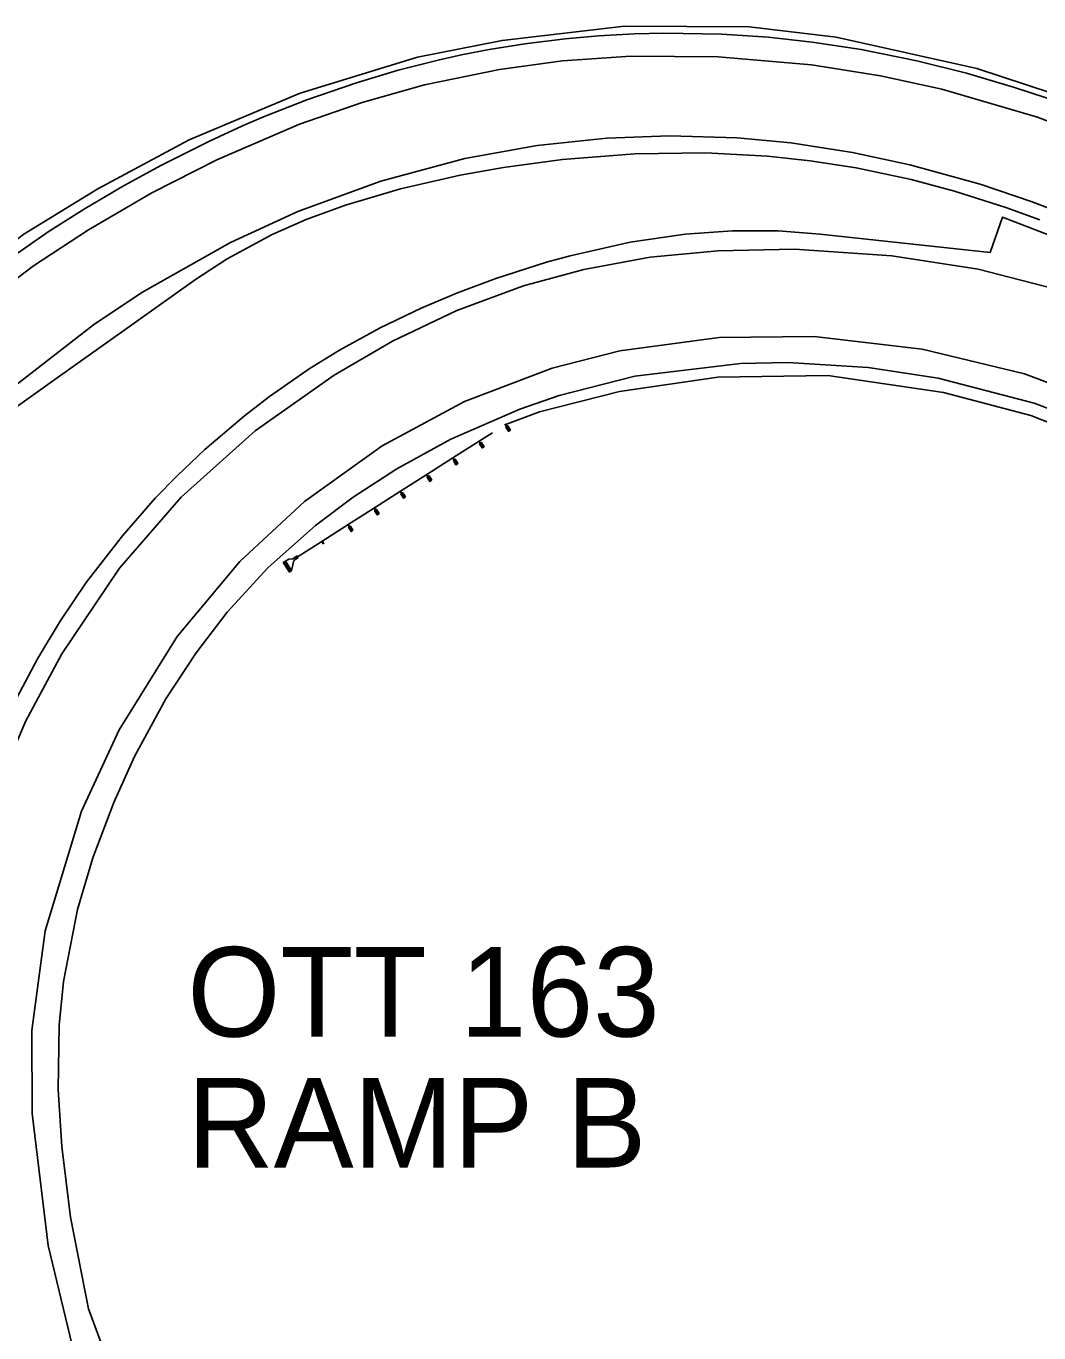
# Model space of a CAD drawing. Extents: x 1855721 to 1876784, y 662259 to 674089.
# Drawn here: x 1856144.7 to 1856348.3, y 673826.6 to 674089.3 of the extents above; entities that cross this region are included whole.
import ezdxf

# ---------------------------------------------------------------- set-up
doc = ezdxf.new("R2010")
doc.units = 0
for name, color, linetype in [('_CIVIL_CONSTRUCTION', 7, 'Continuous'), ('GE_X_Alignment_100_Curve_Data', 7, 'Continuous'), ('RD_P_Anchor_Assembly', 7, 'Continuous'), ('RD_P_GR_Rt', 7, 'Continuous'), ('SC_Scratch1', 7, 'Continuous')]:
    doc.layers.add(name, color=color, linetype=linetype)

msp = doc.modelspace()

# ---------------------------------------------------------------- linework, layer by layer
at = {"layer": '_CIVIL_CONSTRUCTION'}
for points in [[(1856365.83, 674064.19), (1856348.04, 674071.01), (1856328.81, 674076.64), (1856316.49, 674079.35), (1856302.61, 674081.57), (1856283.82, 674083.19), (1856266.25, 674083.26), (1856252.53, 674082.32), (1856239.87, 674080.62), (1856224.82, 674077.52), (1856212.28, 674073.99), (1856199.69, 674069.59), (1856183.06, 674062.46), (1856170, 674055.82), (1856157.25, 674048.4), (1856146.21, 674041.12), (1856132.47, 674030.72)], [(1856153.97, 673824.06), (1856149.12, 673844.11), (1856145.94, 673870.67), (1856145.86, 673887.35), (1856148.51, 673907.38), (1856155.85, 673931.44), (1856163.44, 673947.84), (1856175.09, 673966.57), (1856187.67, 673981.7), (1856200.69, 673993.76), (1856216.3, 674004.93), (1856232.86, 674013.82), (1856250.47, 674020.54), (1856264.09, 674024.02), (1856284, 674026.71), (1856303.15, 674026.89), (1856324.84, 674024.4), (1856345.43, 674019.44), (1856368.74, 674010.66)]]:
    msp.add_lwpolyline(points, dxfattribs=at)
at = {"layer": 'GE_X_Alignment_100_Curve_Data'}
for points in [[(1856023.41, 673851.89), (1856068.46, 673924.1), (1856079.99, 673941.29), (1856102.7, 673972.55), (1856111.82, 673984.94), (1856127.2, 674002.68), (1856142.37, 674016.93), (1856158.23, 674029.27), (1856167.96, 674035.77), (1856185.8, 674045.85), (1856199.32, 674052.06), (1856215.99, 674058.15), (1856232.89, 674062.69), (1856247.41, 674065.32), (1856261.44, 674066.8), (1856274.02, 674067.27), (1856287.62, 674066.87), (1856298.45, 674065.86), (1856310.85, 674063.95), (1856322.36, 674061.47), (1856336.49, 674057.55), (1856346.97, 674054.03), (1856357.92, 674049.8)], [(1856353.26, 674036.03), (1856336.07, 674040.44), (1856318.76, 674043.17), (1856299.16, 674044.45), (1856283.75, 674044.17), (1856270.16, 674042.84), (1856256.79, 674040.42), (1856244.68, 674037.12), (1856231.3, 674032.13), (1856218.37, 674025.96), (1856206.65, 674019.17), (1856190.78, 674007.98), (1856175.89, 673994.63), (1856163.5, 673980.36), (1856151.87, 673963.08), (1856144.68, 673949.64), (1856137.78, 673933.6), (1856132.13, 673915.51), (1856129.25, 673901.08), (1856127.96, 673888.15), (1856127.91, 673872.04), (1856129.26, 673855.64), (1856131.43, 673840.51), (1856134.42, 673826.04)]]:
    msp.add_lwpolyline(points, dxfattribs=at)
at = {"layer": 'RD_P_Anchor_Assembly'}
for p, q in [((1856240.93, 674009.13), (1856241.2, 674009.31)), ((1856240.93, 674009.13), (1856240.94, 674009.12)), ((1856240.94, 674009.12), (1856241.07, 674009.2)), ((1856241.07, 674009.2), (1856241.31, 674008.82)), ((1856241.08, 674009.21), (1856241.21, 674009.3)), ((1856241.08, 674009.21), (1856241.33, 674008.83)), ((1856241.13, 674008.71), (1856241.16, 674008.73)), ((1856241.66, 674007.86), (1856241.13, 674008.7)), ((1856241.15, 674008.84), (1856241.2, 674008.88)), ((1856241.15, 674008.84), (1856241.22, 674008.74)), ((1856241.16, 674008.81), (1856241.23, 674008.86)), ((1856241.16, 674008.74), (1856241.29, 674008.82)), ((1856241.19, 674008.75), (1856241.16, 674008.8)), ((1856241.17, 674008.73), (1856241.16, 674008.74)), ((1856241.18, 674008.71), (1856241.16, 674008.73)), ((1856241.18, 674008.71), (1856241.48, 674008.9)), ((1856241.18, 674008.73), (1856241.31, 674008.82)), ((1856241.18, 674008.73), (1856241.19, 674008.72)), ((1856241.19, 674008.72), (1856241.47, 674008.9)), ((1856241.2, 674009.31), (1856241.21, 674009.3)), ((1856241.2, 674008.88), (1856241.27, 674008.77)), ((1856241.75, 674007.9), (1856241.22, 674008.74)), ((1856241.27, 674008.81), (1856241.24, 674008.85)), ((1856241.81, 674007.94), (1856241.27, 674008.77)), ((1856241.3, 674008.81), (1856241.29, 674008.82)), ((1856241.33, 674008.83), (1856241.46, 674008.91)), ((1856241.46, 674008.91), (1856241.47, 674008.9)), ((1856241.47, 674008.92), (1856241.5, 674008.95)), ((1856241.48, 674008.9), (1856241.47, 674008.92)), ((1856242.05, 674008.1), (1856241.52, 674008.94)), ((1856241.68, 674007.85), (1856242.05, 674008.09)), ((1856230.52, 674002.51), (1856235.79, 674005.87)), ((1856235.65, 674005.78), (1856235.93, 674005.95)), ((1856235.65, 674005.78), (1856235.66, 674005.76)), ((1856235.66, 674005.76), (1856235.8, 674005.85)), ((1856235.79, 674005.87), (1856238.43, 674007.54)), ((1856235.8, 674005.85), (1856236.04, 674005.46)), ((1856235.81, 674005.85), (1856235.94, 674005.94)), ((1856235.81, 674005.85), (1856236.05, 674005.47)), ((1856235.86, 674005.35), (1856235.89, 674005.37)), ((1856236.39, 674004.5), (1856235.86, 674005.34)), ((1856235.88, 674005.49), (1856235.93, 674005.52)), ((1856235.88, 674005.49), (1856235.95, 674005.38)), ((1856235.89, 674005.46), (1856235.95, 674005.5)), ((1856235.89, 674005.38), (1856236.02, 674005.47)), ((1856235.91, 674005.4), (1856235.89, 674005.44)), ((1856235.9, 674005.37), (1856235.89, 674005.38)), ((1856235.91, 674005.35), (1856235.89, 674005.37)), ((1856235.91, 674005.35), (1856236.21, 674005.55)), ((1856235.91, 674005.38), (1856236.04, 674005.46)), ((1856235.91, 674005.38), (1856235.92, 674005.36)), ((1856235.92, 674005.36), (1856236.2, 674005.54)), ((1856235.93, 674005.95), (1856235.94, 674005.94)), ((1856235.93, 674005.52), (1856236, 674005.41)), ((1856236.48, 674004.54), (1856235.95, 674005.38)), ((1856236, 674005.45), (1856235.97, 674005.49)), ((1856236.53, 674004.58), (1856236, 674005.41)), ((1856236.03, 674005.45), (1856236.02, 674005.47)), ((1856236.05, 674005.47), (1856236.19, 674005.55)), ((1856236.19, 674005.55), (1856236.2, 674005.54)), ((1856236.2, 674005.57), (1856236.23, 674005.59)), ((1856236.21, 674005.55), (1856236.2, 674005.57)), ((1856236.78, 674004.75), (1856236.24, 674005.59)), ((1856225.25, 673999.15), (1856230.52, 674002.51)), ((1856230.38, 674002.42), (1856230.66, 674002.6)), ((1856230.38, 674002.42), (1856230.39, 674002.41)), ((1856230.39, 674002.41), (1856230.53, 674002.49)), ((1856230.53, 674002.49), (1856230.77, 674002.1)), ((1856230.54, 674002.5), (1856230.67, 674002.58)), ((1856230.54, 674002.5), (1856230.78, 674002.11)), ((1856230.66, 674002.6), (1856230.67, 674002.58)), ((1856236.41, 674004.5), (1856236.78, 674004.73)), ((1856230.59, 674002), (1856230.62, 674002.02)), ((1856231.12, 674001.14), (1856230.59, 674001.98)), ((1856230.61, 674002.13), (1856230.66, 674002.16)), ((1856230.61, 674002.13), (1856230.68, 674002.02)), ((1856230.62, 674002.1), (1856230.68, 674002.14)), ((1856230.62, 674002.02), (1856230.75, 674002.11)), ((1856230.64, 674002.04), (1856230.62, 674002.08)), ((1856230.63, 674002.01), (1856230.62, 674002.02)), ((1856230.63, 674002), (1856230.62, 674002.02)), ((1856230.63, 674002), (1856230.94, 674002.19)), ((1856230.64, 674002.02), (1856230.77, 674002.1)), ((1856230.64, 674002.02), (1856230.65, 674002.01)), ((1856230.65, 674002.01), (1856230.92, 674002.18)), ((1856230.66, 674002.16), (1856230.73, 674002.06)), ((1856231.21, 674001.19), (1856230.68, 674002.02)), ((1856230.72, 674002.09), (1856230.7, 674002.14)), ((1856231.26, 674001.22), (1856230.73, 674002.06)), ((1856230.76, 674002.1), (1856230.75, 674002.11)), ((1856230.78, 674002.11), (1856230.92, 674002.2)), ((1856230.92, 674002.2), (1856230.92, 674002.18)), ((1856230.93, 674002.21), (1856230.96, 674002.23)), ((1856230.94, 674002.19), (1856230.93, 674002.21)), ((1856231.51, 674001.39), (1856230.97, 674002.23)), ((1856231.13, 674001.14), (1856231.5, 674001.38)), ((1856219.98, 673995.79), (1856225.25, 673999.15)), ((1856225.11, 673999.06), (1856225.39, 673999.24)), ((1856225.11, 673999.06), (1856225.12, 673999.05)), ((1856225.12, 673999.05), (1856225.25, 673999.13)), ((1856225.25, 673999.13), (1856225.5, 673998.75)), ((1856225.27, 673999.14), (1856225.4, 673999.22)), ((1856225.27, 673999.14), (1856225.51, 673998.76)), ((1856225.85, 673997.79), (1856225.31, 673998.62)), ((1856225.32, 673998.64), (1856225.35, 673998.66)), ((1856225.34, 673998.77), (1856225.39, 673998.81)), ((1856225.34, 673998.74), (1856225.41, 673998.78)), ((1856225.34, 673998.77), (1856225.4, 673998.67)), ((1856225.37, 673998.68), (1856225.34, 673998.73)), ((1856225.35, 673998.67), (1856225.48, 673998.75)), ((1856225.35, 673998.66), (1856225.35, 673998.67)), ((1856225.36, 673998.64), (1856225.35, 673998.66)), ((1856225.36, 673998.64), (1856225.67, 673998.83)), ((1856225.37, 673998.66), (1856225.5, 673998.75)), ((1856225.37, 673998.66), (1856225.38, 673998.65)), ((1856225.38, 673998.65), (1856225.65, 673998.82)), ((1856225.39, 673999.24), (1856225.4, 673999.22)), ((1856225.39, 673998.81), (1856225.46, 673998.7)), ((1856225.94, 673997.83), (1856225.4, 673998.67)), ((1856225.45, 673998.74), (1856225.43, 673998.78)), ((1856225.99, 673997.86), (1856225.46, 673998.7)), ((1856225.49, 673998.74), (1856225.48, 673998.75)), ((1856225.51, 673998.76), (1856225.64, 673998.84)), ((1856225.64, 673998.84), (1856225.65, 673998.82)), ((1856225.65, 673998.85), (1856225.69, 673998.87)), ((1856225.67, 673998.83), (1856225.65, 673998.85)), ((1856226.24, 673998.03), (1856225.7, 673998.87)), ((1856225.86, 673997.78), (1856226.23, 673998.02)), ((1856214.71, 673992.44), (1856219.98, 673995.79)), ((1856219.84, 673995.71), (1856220.12, 673995.88)), ((1856219.84, 673995.71), (1856219.85, 673995.69)), ((1856219.85, 673995.69), (1856219.98, 673995.78)), ((1856219.98, 673995.78), (1856220.23, 673995.39)), ((1856219.99, 673995.78), (1856220.13, 673995.87)), ((1856219.99, 673995.78), (1856220.24, 673995.4)), ((1856220.04, 673995.28), (1856220.08, 673995.3)), ((1856220.58, 673994.43), (1856220.04, 673995.27)), ((1856220.06, 673995.42), (1856220.12, 673995.45)), ((1856220.06, 673995.42), (1856220.13, 673995.31)), ((1856220.07, 673995.38), (1856220.14, 673995.43)), ((1856220.07, 673995.31), (1856220.21, 673995.39)), ((1856220.1, 673995.33), (1856220.07, 673995.37)), ((1856220.08, 673995.3), (1856220.07, 673995.31)), ((1856220.09, 673995.28), (1856220.08, 673995.3)), ((1856220.09, 673995.28), (1856220.39, 673995.48)), ((1856220.09, 673995.31), (1856220.23, 673995.39)), ((1856220.09, 673995.31), (1856220.1, 673995.29)), ((1856220.1, 673995.29), (1856220.38, 673995.47)), ((1856220.12, 673995.88), (1856220.13, 673995.87)), ((1856220.12, 673995.45), (1856220.19, 673995.34)), ((1856220.66, 673994.47), (1856220.13, 673995.31)), ((1856220.18, 673995.38), (1856220.15, 673995.42)), ((1856220.72, 673994.51), (1856220.19, 673995.34)), ((1856220.21, 673995.38), (1856220.21, 673995.39)), ((1856220.24, 673995.4), (1856220.37, 673995.48)), ((1856220.37, 673995.48), (1856220.38, 673995.47)), ((1856220.38, 673995.5), (1856220.42, 673995.52)), ((1856220.39, 673995.48), (1856220.38, 673995.5)), ((1856220.96, 673994.67), (1856220.43, 673995.51)), ((1856220.59, 673994.42), (1856220.96, 673994.66)), ((1856209.43, 673989.08), (1856214.71, 673992.44)), ((1856214.57, 673992.35), (1856214.84, 673992.53)), ((1856214.57, 673992.35), (1856214.58, 673992.33)), ((1856214.58, 673992.33), (1856214.71, 673992.42)), ((1856214.71, 673992.42), (1856214.96, 673992.03)), ((1856214.72, 673992.43), (1856214.85, 673992.51)), ((1856214.72, 673992.43), (1856214.97, 673992.04)), ((1856214.77, 673991.92), (1856214.81, 673991.94)), ((1856215.3, 673991.07), (1856214.77, 673991.91)), ((1856214.79, 673992.06), (1856214.85, 673992.09)), ((1856214.79, 673992.06), (1856214.86, 673991.95)), ((1856214.8, 673992.03), (1856214.87, 673992.07)), ((1856214.8, 673991.95), (1856214.93, 673992.04)), ((1856214.83, 673991.97), (1856214.8, 673992.01)), ((1856214.81, 673991.94), (1856214.8, 673991.95)), ((1856214.82, 673991.92), (1856214.81, 673991.94)), ((1856214.82, 673991.92), (1856215.12, 673992.12)), ((1856214.82, 673991.95), (1856214.96, 673992.03)), ((1856214.82, 673991.95), (1856214.83, 673991.93)), ((1856214.83, 673991.93), (1856215.11, 673992.11)), ((1856214.84, 673992.53), (1856214.85, 673992.51)), ((1856214.85, 673992.09), (1856214.91, 673991.99)), ((1856215.39, 673991.12), (1856214.86, 673991.95)), ((1856214.91, 673992.02), (1856214.88, 673992.06)), ((1856215.45, 673991.15), (1856214.91, 673991.99)), ((1856214.94, 673992.02), (1856214.93, 673992.04)), ((1856214.97, 673992.04), (1856215.1, 673992.13)), ((1856215.1, 673992.13), (1856215.11, 673992.11)), ((1856215.11, 673992.14), (1856215.14, 673992.16)), ((1856215.12, 673992.12), (1856215.11, 673992.14)), ((1856215.69, 673991.32), (1856215.16, 673992.16)), ((1856215.32, 673991.07), (1856215.69, 673991.3)), ((1856204.16, 673985.72), (1856209.43, 673989.08)), ((1856209.3, 673988.99), (1856209.57, 673989.17)), ((1856209.3, 673988.99), (1856209.31, 673988.98)), ((1856209.31, 673988.98), (1856209.44, 673989.06)), ((1856209.44, 673989.06), (1856209.68, 673988.68)), ((1856209.45, 673989.07), (1856209.58, 673989.15)), ((1856209.45, 673989.07), (1856209.7, 673988.68)), ((1856209.5, 673988.57), (1856209.53, 673988.59)), ((1856210.03, 673987.71), (1856209.5, 673988.55)), ((1856209.52, 673988.7), (1856209.57, 673988.73)), ((1856209.52, 673988.7), (1856209.59, 673988.59)), ((1856209.53, 673988.67), (1856209.6, 673988.71)), ((1856209.53, 673988.6), (1856209.66, 673988.68)), ((1856209.55, 673988.61), (1856209.53, 673988.65)), ((1856209.54, 673988.58), (1856209.53, 673988.6)), ((1856209.55, 673988.57), (1856209.53, 673988.59)), ((1856209.55, 673988.57), (1856209.85, 673988.76)), ((1856209.55, 673988.59), (1856209.68, 673988.68)), ((1856209.55, 673988.59), (1856209.56, 673988.58)), ((1856209.56, 673988.58), (1856209.84, 673988.75)), ((1856209.57, 673989.17), (1856209.58, 673989.15)), ((1856209.57, 673988.73), (1856209.64, 673988.63)), ((1856210.12, 673987.76), (1856209.59, 673988.59)), ((1856209.64, 673988.66), (1856209.61, 673988.71)), ((1856210.17, 673987.79), (1856209.64, 673988.63)), ((1856209.67, 673988.67), (1856209.66, 673988.68)), ((1856209.7, 673988.68), (1856209.83, 673988.77)), ((1856209.83, 673988.77), (1856209.84, 673988.75)), ((1856209.84, 673988.78), (1856209.87, 673988.8)), ((1856209.85, 673988.76), (1856209.84, 673988.78)), ((1856210.42, 673987.96), (1856209.89, 673988.8)), ((1856210.05, 673987.71), (1856210.42, 673987.95)), ((1856198.89, 673982.37), (1856204.16, 673985.72)), ((1856204.11, 673985.69), (1856204.38, 673985.86)), ((1856204.12, 673985.67), (1856204.11, 673985.69)), ((1856204.12, 673985.67), (1856204.25, 673985.76)), ((1856204.14, 673985.71), (1856204.39, 673985.31)), ((1856204.19, 673985.74), (1856204.44, 673985.34)), ((1856204.49, 673985.37), (1856204.25, 673985.76)), ((1856204.26, 673985.76), (1856204.39, 673985.85)), ((1856204.51, 673985.38), (1856204.26, 673985.76)), ((1856204.36, 673985.29), (1856204.49, 673985.37)), ((1856204.37, 673985.27), (1856204.36, 673985.29)), ((1856204.36, 673985.26), (1856204.37, 673985.25)), ((1856204.37, 673985.27), (1856204.65, 673985.45)), ((1856204.37, 673985.25), (1856204.5, 673985.34)), ((1856204.39, 673985.85), (1856204.38, 673985.86)), ((1856204.46, 673985.2), (1856204.39, 673985.31)), ((1856204.39, 673985.27), (1856204.42, 673985.23)), ((1856204.43, 673985.22), (1856204.5, 673985.26)), ((1856204.51, 673985.23), (1856204.44, 673985.34)), ((1856204.46, 673985.2), (1856204.51, 673985.23)), ((1856204.48, 673985.32), (1856204.5, 673985.28)), ((1856204.49, 673985.35), (1856204.5, 673985.34)), ((1856204.51, 673985.38), (1856204.64, 673985.46)), ((1856204.65, 673985.45), (1856204.64, 673985.46))]:
    msp.add_line(p, q, dxfattribs=at)
for centre, start, end in [((1856241.14, 674008.7), 122.4895, 212.4895), ((1856241.51, 674008.94), 32.4895, 122.4895), ((1856241.67, 674007.86), 212.4895, 302.4895), ((1856242.04, 674008.1), 302.4895, 32.4895), ((1856235.87, 674005.34), 122.4895, 212.4895), ((1856236.24, 674005.58), 32.4895, 122.4895), ((1856236.4, 674004.5), 212.4895, 302.4895), ((1856236.77, 674004.74), 302.4895, 32.4895), ((1856230.59, 674001.99), 122.4895, 212.4895), ((1856230.96, 674002.22), 32.4895, 122.4895), ((1856231.13, 674001.15), 212.4895, 302.4895), ((1856231.5, 674001.38), 302.4895, 32.4895), ((1856225.32, 673998.63), 122.4895, 212.4895), ((1856225.69, 673998.87), 32.4895, 122.4895), ((1856225.86, 673997.79), 212.4895, 302.4895), ((1856226.23, 673998.03), 302.4895, 32.4895), ((1856220.05, 673995.27), 122.4895, 212.4895), ((1856220.42, 673995.51), 32.4895, 122.4895), ((1856220.95, 673994.67), 302.4895, 32.4895), ((1856214.78, 673991.92), 122.4895, 212.4895), ((1856215.15, 673992.15), 32.4895, 122.4895), ((1856220.58, 673994.43), 212.4895, 302.4895), ((1856215.31, 673991.08), 212.4895, 302.4895), ((1856215.68, 673991.31), 302.4895, 32.4895), ((1856209.51, 673988.56), 122.4895, 212.4895), ((1856209.88, 673988.79), 32.4895, 122.4895), ((1856210.04, 673987.72), 212.4895, 302.4895), ((1856210.41, 673987.95), 302.4895, 32.4895)]:
    msp.add_arc(centre, 0.01, start, end, dxfattribs=at)
for centre, major_axis, ratio, start_param, end_param in [((1856241.17, 674008.8), (0.0075, -0.0117), 0.929688, 3.345604, 4.722982), ((1856241.23, 674008.84), (0.0075, -0.0118), 0.929688, 1.586202, 2.897406), ((1856241.78, 674007.92), (0.088, 0.0561), 0.312583, 3.061844, 6.362934), ((1856235.9, 674005.45), (0.0075, -0.0117), 0.929688, 3.345604, 4.722982), ((1856235.96, 674005.48), (0.0075, -0.0118), 0.929688, 1.586202, 2.897406), ((1856236.51, 674004.56), (0.088, 0.0561), 0.312583, 3.061844, 6.362934), ((1856230.63, 674002.09), (0.0075, -0.0117), 0.929688, 3.345604, 4.722982), ((1856230.69, 674002.13), (0.0075, -0.0118), 0.929688, 1.586202, 2.897406), ((1856231.24, 674001.2), (0.088, 0.0561), 0.312583, 3.061844, 6.362934), ((1856225.35, 673998.73), (0.0075, -0.0117), 0.929688, 3.345604, 4.722982), ((1856225.42, 673998.77), (0.0075, -0.0118), 0.929688, 1.586202, 2.897406), ((1856225.96, 673997.84), (0.088, 0.0561), 0.312583, 3.061844, 6.362934), ((1856220.08, 673995.37), (0.0075, -0.0117), 0.929688, 3.345604, 4.722982), ((1856220.14, 673995.41), (0.0075, -0.0118), 0.929688, 1.586202, 2.897406), ((1856220.69, 673994.49), (0.088, 0.0561), 0.312583, 3.061844, 6.362934), ((1856214.81, 673992.02), (0.0075, -0.0117), 0.929688, 3.345604, 4.722982), ((1856214.87, 673992.06), (0.0075, -0.0118), 0.929688, 1.586202, 2.897406), ((1856215.42, 673991.13), (0.088, 0.0561), 0.312583, 3.061844, 6.362934), ((1856209.54, 673988.66), (0.0075, -0.0117), 0.929688, 3.345604, 4.722982), ((1856209.6, 673988.7), (0.0075, -0.0118), 0.929688, 1.586202, 2.897406), ((1856210.15, 673987.77), (0.088, 0.0561), 0.312583, 3.061844, 6.362934), ((1856204.16, 673985.73), (0.088, 0.0561), 0.312583, 6.203436, 9.504527), ((1856204.43, 673985.23), (-0.0075, 0.0117), 0.929688, 1.560203, 2.937581), ((1856204.49, 673985.27), (-0.0075, 0.0118), 0.929688, 3.385779, 4.696983)]:
    msp.add_ellipse(centre, major_axis=major_axis, ratio=ratio, start_param=start_param, end_param=end_param, dxfattribs=at)
at = {"layer": 'RD_P_GR_Rt'}
for p, q in [((1856197.63, 673979.55), (1856196.4, 673981.45)), ((1856197.92, 673979.74), (1856196.69, 673981.63)), ((1856198.09, 673979.85), (1856196.87, 673981.74)), ((1856198.09, 673979.85), (1856198.53, 673981.89)), ((1856199.17, 673982.78), (1856198.31, 673982.23)), ((1856199.39, 673982.45), (1856198.53, 673981.89)), ((1856199.39, 673982.45), (1856199.17, 673982.78)), ((1856198.09, 673979.85), (1856197.63, 673979.55))]:
    msp.add_line(p, q, dxfattribs=at)
for points in [[(1856361.08, 674072.5), (1856335.84, 674080.82), (1856307.52, 674087.08), (1856290.04, 674089.22), (1856264.99, 674089.33), (1856240.38, 674086.45), (1856223.36, 674083.08), (1856199.77, 674075.88), (1856177.46, 674066.48), (1856159.13, 674056.64), (1856144.23, 674047.51), (1856124.5, 674032.33), (1856111.91, 674020.42), (1856098.27, 674006.12), (1856091.27, 673997.3), (1856080.63, 673983.38), (1856058.22, 673952.99)], [(1856240.93, 674009.13), (1856247.88, 674011.8), (1856263.98, 674015.83), (1856283.75, 674018.73), (1856305.9, 674019.06), (1856329.09, 674015.69), (1856346.68, 674011.02), (1856366.55, 674003.19), (1856382.24, 673995.18), (1856404.44, 673981.21), (1856418.37, 673970.76), (1856438.1, 673953.57), (1856455.26, 673936.66), (1856477.92, 673910.81), (1856499.45, 673885.56), (1856544.95, 673831.46)], [(1856196.4, 673981.45), (1856197.55, 673982.17), (1856198.31, 673982.23)]]:
    msp.add_lwpolyline(points, dxfattribs=at)
at = {"layer": 'SC_Scratch1'}
for points in [[(1856352.85, 674073.9), (1856343.42, 674077.02), (1856333.75, 674079.84), (1856323.78, 674082.33), (1856312.56, 674084.61), (1856302.7, 674086.13), (1856293.85, 674087.1), (1856284.59, 674087.72), (1856272.88, 674087.92), (1856266.99, 674087.78), (1856259.8, 674087.38), (1856253.1, 674086.79), (1856244.94, 674085.77), (1856237.77, 674084.61), (1856232.23, 674083.54), (1856227.78, 674082.56), (1856219.53, 674080.46), (1856211.14, 674077.96), (1856201.11, 674074.49), (1856192.44, 674071.07), (1856188.24, 674069.27), (1856181.72, 674066.29), (1856171.95, 674061.4), (1856164.43, 674057.29), (1856156.56, 674052.65), (1856149.37, 674048.07), (1856141.54, 674042.67)], [(1856142.02, 674012.22), (1856150.49, 674018.25), (1856166.42, 674029.58), (1856178.76, 674038.36), (1856185.11, 674042.52), (1856194.2, 674047.42), (1856200.98, 674050.42), (1856208.88, 674053.35), (1856220, 674056.63), (1856231.93, 674059.33), (1856240.69, 674060.9), (1856252.55, 674062.52), (1856267.05, 674063.68), (1856281.27, 674063.87), (1856293.76, 674063.2), (1856302.3, 674062.27), (1856311.6, 674060.81), (1856322.61, 674058.47), (1856331.33, 674056.16), (1856341.64, 674052.89), (1856348.47, 674050.41)], [(1856352.65, 674046.4), (1856340.95, 674050.94), (1856338.48, 674043.84), (1856304.33, 674047.52), (1856295.86, 674048.15), (1856286.7, 674048.16), (1856277.17, 674047.48), (1856266.15, 674045.87), (1856254.07, 674043.16), (1856249.3, 674041.85), (1856239.13, 674038.61), (1856231.4, 674035.71), (1856224.1, 674032.61), (1856215.91, 674028.66), (1856207.71, 674024.15), (1856201.64, 674020.4), (1856193.62, 674014.84), (1856188.58, 674010.98), (1856180.61, 674004.19), (1856175.15, 673999), (1856170.68, 673994.39), (1856164.07, 673986.86), (1856156.81, 673977.45), (1856151.56, 673969.7), (1856146.98, 673962.13), (1856141.05, 673950.85)], [(1856162.85, 673816.19), (1856157.28, 673831.42), (1856153.65, 673849.83), (1856151.9, 673864.03), (1856151.17, 673875.51), (1856151.35, 673888.45), (1856152.22, 673897.2), (1856155.04, 673911.66), (1856158.11, 673922.08), (1856162.31, 673933.19), (1856166.53, 673942.44), (1856172.82, 673954.03), (1856178.88, 673963.33), (1856185.14, 673971.48), (1856193.4, 673980.46), (1856202.88, 673988.89), (1856210.47, 673994.61), (1856219.26, 674000.32), (1856230.08, 674006.26), (1856243.94, 674012.32), (1856251.86, 674015.06), (1856267.08, 674018.91), (1856288.33, 674021.49), (1856297.81, 674021.68), (1856314, 674020.7), (1856328.06, 674018.52), (1856347.37, 674013.49), (1856362.63, 674007.78)]]:
    msp.add_lwpolyline(points, dxfattribs=at)

# ---------------------------------------------------------------- texts
for s, p in [('OTT 163', (1856177.11, 673886.14)), ('RAMP B', (1856177.11, 673859.81))]:
    msp.add_text(s, height=18, dxfattribs=at).set_placement(p)

doc.saveas('drawing.dxf')
